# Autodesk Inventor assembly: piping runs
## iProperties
Name: ISO 2531 - Flanged Ductile Iron Pipe and Fittings
ActiveState: False
PipeType: Rigid Pipe
RoutePreview: Solid
Material: UnInitValue
Standard: UnInitValue
FittingMaterial: UnInitValue
FittingStandard: UnInitValue
RouteDirection90: True
RouteDirection45: True
DiameterType: Nominal
Diameter: M40
Schedule: PN10
Ending: UnInitValue
IntermediateSegmentsMin: 1000.000 mm
IntermediateSegmentsMax: 9000.000 mm
IntermediateSegmentsInc: 10.000 mm
TerminationSegmentsMin: 1000.000 mm
TerminationSegmentsMax: 9000.000 mm
TerminationSegmentsInc: 10.000 mm
SolidRoutePreviewColor: 12632064
PipingComponentColor: As Material
PipeKey: v3#f52fbdcb-ece8-4303-8b76-5dbe8c7f2f9c#16
Elbow90Key: v3#451ae64e-c79d-4cba-b533-c09b8090ecb2#1
Elbow45Key: v3#81684a3f-f2a4-4fe6-95b1-f067ddead22f#1
_ComponentInfo: <CS><C N="Pipe" R="2.700000" IR="2.000000" PL="PL" PN="ISO 2531 Pipe with Integrally Cast Flanges DN40 PN 10"><CO N="1"><FE V="0"/><FD V="0"/><ET  V="Flanged"/>
BendRadius: UnInitValue
CategoryName: UnInitValue
DefaultBendRadius: UnInitValue
EndFittingKey: UnInitValue
FlangeKey: UnInitValue
Gap: UnInitValue
GasketKey: UnInitValue
IsButtWelded: UnInitValue
IsFlanged: UnInitValue
MixedUnits: UnInitValue
RoundUpValue: UnInitValue
ShowGap: UnInitValue
StartFittingKey: UnInitValue
SuppressEndFitting: UnInitValue
SuppressStartFitting: UnInitValue
UseFlangsForCouplings: UnInitValue
UseSubASM: UnInitValue
Name: Hydraulic Hose - SAE Flanged Connection
PipeType: Flexible Hose
RouteDirection90: UnInitValue
RouteDirection45: UnInitValue
Diameter: 1/2
Schedule: ID=0.5
OD: 2.235200000000000e+000
ID: 1.270000000000000e+000
IntermediateSegmentsMin: UnInitValue
IntermediateSegmentsMax: UnInitValue
IntermediateSegmentsInc: UnInitValue
TerminationSegmentsMin: UnInitValue
TerminationSegmentsMax: UnInitValue
TerminationSegmentsInc: UnInitValue
RoundUpValue: 0.125 in
PipeKey: v3#d489867e-ac9b-47ea-b952-0a1b885f66be#4
CouplingKey: UnInitValue
Elbow90Key: UnInitValue
Elbow45Key: UnInitValue
_ComponentInfo: <CS><C N="Pipe" R="1.117600" OR="1.117600" IR="0.635000" PL="PL" PartType="" SymKey="" PN="Parker Hydraulic Hose - No Skive 1/2"><CO N="1"><FE V="0"/><FD V="0"/
BendRadius: 0.500 in
StartFittingKey: v3#933069c9-73b6-4141-af99-628d4a97b2c2#1
EndFittingKey: v3#933069c9-73b6-4141-af99-628d4a97b2c2#1
SuppressStartFitting: False
SuppressEndFitting: False
UseSubASM: True
Name: Hydraulic Hose - Female Taper Thread
StartFittingKey: v3#cc3bd835-95a2-497d-9893-176cd9c426f6#7
EndFittingKey: v3#cc3bd835-95a2-497d-9893-176cd9c426f6#7
Name: JIS G 3458/JIS B 2316 -  Welded Steel Pipe and Fittings
Schedule: 80
IntermediateSegmentsMin: 60.000 mm
IntermediateSegmentsMax: 5000.000 mm
IntermediateSegmentsInc: 1.000 mm
TerminationSegmentsMin: 60.000 mm
TerminationSegmentsMax: 5000.000 mm
TerminationSegmentsInc: 1.000 mm
PipeKey: v3#da14b0ab-0b36-4851-8d66-8c9cd0bcbe86#23
CouplingKey: v3#12b64993-10e6-4915-8315-0c0cce209ad0#8
Elbow90Key: v3#1f65ece3-c41a-48d4-8661-909ed34ade86#8
Elbow45Key: v3#28e76e79-e22c-40ab-8be2-ff545b1407c5#8
_ComponentInfo: <CS><C N="Pipe" R="2.430000" IR="1.920000" PL="PL" PN="JIS G 3458 Pipe 40 A x Sch 80"><CO N="1"><FE V="0"/><FD V="1"/><ET V="Welded"/><NS  V="M40"/><MA V="0.000
Name: ASTM A53/A53M-ASME B16.11 - Welded Steel Pipe
Material: Steel
Standard: ASTM A 53/A 53M
FittingMaterial: Steel
FittingStandard: ASME B16.11
Schedule: 40
OD: Undefined
ID: Undefined
IntermediateSegmentsMin: 1.000 in
IntermediateSegmentsMax: 200.000 in
IntermediateSegmentsInc: 0.100 in
TerminationSegmentsMin: 1.000 in
TerminationSegmentsMax: 200.000 in
TerminationSegmentsInc: 0.100 in
PipeKey: v3#4ce5e9fa-6da0-4801-ac02-ee7a0fb518d6#7
CouplingKey: v3#ed415c76-4cec-44a3-ba67-72e47bf70384#4
Elbow90Key: v3#82a08401-12d7-413b-b7f9-9cf3b607be7b#4
Elbow45Key: v3#2e5fd082-3851-4eb0-bde1-6c7078a7d72b#4
_ComponentInfo: <CS><C N="Pipe" R="1.066800" IR="0.789940" PL="PL" PN="ASTM A 53/A 53M Pipe 1/2 - Schedule 40"><CO N="1"><FE V="0"/><FD V="0"/><ET V="Welded"/><NS  V="1/2"/><MA
Diameter: 6
Elbow90Key: v3#97ecdcaf-8aa3-4fb0-8b6a-3da783de2ad5#108
Gap: 0.062 inch
ID: UnInitValue
IntermediateSegmentsInc: 0.00001 in
IntermediateSegmentsMax: 200 inch
IntermediateSegmentsMin: 3 inch
IsButtWelded: True
IsFlanged: False
Name: ASTM A 53/A-ASME B16.9 - Steel Butt Welded Pipe
OD: UnInitValue
PipeKey: v3#4ce5e9fa-6da0-4801-ac02-ee7a0fb518d6#77
RouteDirection45: False
ShowGap: True
TerminationSegmentsInc: 0.00001 in
TerminationSegmentsMax: 200 inch
TerminationSegmentsMin: 3 inch
_ComponentInfo: <CS><C N="Elbow90" ER="15.240000" S1="15.240000" S2="15.240000" D1="0.000000" D2="0.000000" PartType="fitting" SymKey="ELBW"><CO N="1"><FE V="2"/><FD V="0"/><ET
MixedUnits: False
Created: 2006-09
Part Number: piping runs
Document SubType Name: Tube & Pipe
Designer: Autodesk
Manufacturer: Standard
Standards Organization: Custom
Angle: 92.00 deg
Diameter: 1
Elbow45Key: v3#bf26aa2a-f3dd-474c-8758-922a145c2b02#15
Elbow90Key: v3#3e93288f-9bb7-4e46-9d6b-544f8c20ca1c#3
ElbowCustomKey: v3#1f3bd44a-47ab-42f9-b3e0-74afa0c3f0ca#3
Gap: 0.094 in
IntermediateSegmentsMin: 2.000 in
IsSelfDraining: True
Name: ASME BPE - Butt Welded
PipeKey: v3#b10c956f-6fc6-429e-8056-0864a8581764#35
Schedule: ID=0.87
TerminationSegmentsMin: 2.000 in
_ComponentInfo: <CS><C N="Pipe" R="1.270000" OR="1.270000" IR="1.104900" PL="PL" PartType="pipe" SymKey="" PN="ASTM A 269 Tube with Welded ends 1 x 0.87"><CO N="1"><FE V="2"/><
Elbow90Key: v3#6a678020-d9d9-4685-bba9-906b9a167083#10
FlangeKey: v3#c11442d2-c568-438f-a870-8ac9b5b636cb#10
GasketKey: v3#2a41914c-f5fb-4682-9c6a-1870d826d3d0#23
IntermediateSegmentsInc: 0.1 inch
IsButtWelded: False
IsFlanged: True
Name: ASTM A 53/A-ASME B16.5 - Flanged Steel Threaded Pipe
PipeKey: v3#c5bd7d28-cdb3-4507-9f3d-c2787d93fe8a#40
TerminationSegmentsInc: 0.1 inch
_ComponentInfo: <CS><C N="Elbow90" ER="21.590000" S1="21.590000" S2="21.590000" D1="0.000000" D2="0.000000" PartType="fitting" SymKey="ELFL"><CO N="1"><FE V="2"/><FD V="1"/><ET
ElbowCustomKey: UnInitValue
IsSelfDraining: False
Name: ASME B36.10M-ASME B16.11 - Steel Threaded Pipe
ActiveState: True
Material: Wrought Steel
Standard: ASME B36.10M
Schedule: 30
OD: 2.1336
ID: 1.651
PipeKey: v3#4a736116-503a-44ad-a922-868ac6b46736#1
CouplingKey: v3#52ad3977-2b89-4007-a6a6-7626bac0ae85#4
Elbow90Key: v3#160eac10-3e6f-4b5c-839c-61eee0d373dc#4
Elbow45Key: v3#5c2ab816-abcb-49a6-a106-4733af000f51#4
_ComponentInfo: <CS><C N="Pipe" R="1.066800" IR="0.825500" PL="PL" PN="ASME B36.10M Pipe with Threaded Ends 1/2 - Schedule 30"><CO N="1"><FE V="0"/><FD V="1"/><ET  V="Threaded"
Name: DIN 2458/DIN 2605 - Welded Steel Pipe and Fittings
Schedule: ID=30.7
PipeKey: v3#dcef2839-8903-4c98-a96c-b861f5d9bb7f#98
Elbow90Key: v3#ace818b0-7b7c-4ad9-b19c-6da358a202c1#17
Elbow45Key: v3#97879d80-057e-491b-840b-74a9b3a7cf63#17
_ComponentInfo: <CS><C N="Pipe" R="2.415000" IR="1.535000" PL="PL" PN="DIN 2458 Pipe 48.3 x 8.8"><CO N="1"><FE V="2"/><FD V="0"/><ET V="Welded"/><NS V="M40"/><MA  V="0.000000"/
Name: Hydraulic Hose - Male Taper Thread
StartFittingKey: v3#c8250148-a7b6-458b-b7bd-3b56763ca7cc#13
EndFittingKey: v3#c8250148-a7b6-458b-b7bd-3b56763ca7cc#13
Name: JIS G 3442/JIS B 2301 Threaded Steel Pipe and Iron Fittings
Schedule: ID=16.1
IntermediateSegmentsMin: 20.000 mm
TerminationSegmentsMin: 20.000 mm
PipeKey: v3#9964fba4-9d5a-4d75-85a8-e38022ccdce1#2
CouplingKey: v3#181262db-c004-4877-bc40-c64b931a44f6#3
Elbow90Key: v3#6c92b367-65e9-486b-b952-db434ae2548d#3
Elbow45Key: v3#960407aa-00b9-4d72-aae7-d50595845cfd#3
_ComponentInfo: <CS><C N="Pipe" R="1.085000" IR="0.805000" PL="PL" PN="JIS G 3442 Pipe with Threaded Ends 21.7 x 2.8"><CO N="1"><FE V="0"/><FD V="1"/><ET V="Threaded"/><NS V="1
Name: ASTM B 88-ASME B16.22 - Soldered Copper Tubing
PipeType: Tubing
Material: Copper
Standard: ASTM B 88
FittingMaterial: *
FittingStandard: ASME B16.22
Schedule: L
IntermediateSegmentsMin: 0.000 in
IntermediateSegmentsMax: 100.000 in
TerminationSegmentsMin: 0.000 in
TerminationSegmentsMax: 100.000 in
SolidRoutePreviewColor: 49344
PipeKey: v3#44b182c9-4bce-4825-bb4d-596143122252#7
CouplingKey: v3#0dc1ae02-7bbf-4ccf-8498-581434b0a765#3
_ComponentInfo: <CS><C N="Pipe" R="0.793750" IR="0.692150" PL="PL" PN="ASTM B 88 Tube 1/2 - Type L"><CO N="1"><FE V="0"/><FD V="0"/><ET V="Soldered"/><NS V="1/2"/><MA V="2.5400
DefaultBendRadius: 2.000 in
Name: ISO 7598/ISO 49 - Threaded Steel Pipe with Iron Fittings
IntermediateSegmentsMin: 50.800 mm
IntermediateSegmentsMax: 5080.000 mm
IntermediateSegmentsInc: 2.540 mm
TerminationSegmentsMin: 50.800 mm
TerminationSegmentsMax: 5080.000 mm
TerminationSegmentsInc: 2.540 mm
PipeKey: v3#1052637f-74b5-47f4-adeb-d4e8d3fa53b8#1
CouplingKey: v3#7e56b2cb-a132-4546-b8a7-a14538454b94#3
Elbow90Key: v3#b72bb08b-ad33-47cc-a03d-7f3d76c6616b#3
Elbow45Key: v3#a96c5204-26e4-4bb2-b8f1-f0623fbc94bb#2
_ComponentInfo: <CS><C N="Pipe" R="1.065000" IR="0.805000" PL="PL" PN="ISO 7598 Tube with Threaded Ends DN15"><CO N="1"><FE V="0"/><FD V="1"/><ET V="Threaded"/><NS V="1/2"/><MA
FlangeKey: v3#24991861-26e3-4c21-a713-f46e314eddd5#10
IntermediateSegmentsMin: 3.000 in
Name: ASTM A 53/A 53M - Butt Welded/Flanged Steel Pipe
TerminationSegmentsMin: 3.000 in
UseFlangsForCouplings: False
_ComponentInfo: <CS><C N="Pipe" R="8.413750" OR="8.413750" IR="7.702550" PL="PL" PartType="pipe" SymKey="" PN="ASTM A 53/A 53M Pipe 6 - Schedule 40"><CO N="1"><FE V="2"/><FD V=
Name: JIS K 6741/JIS K 6739 - Jointed PVC-U Pipe and Fittings
Schedule: VP
IntermediateSegmentsMax: 2500.000 mm
TerminationSegmentsMax: 2500.000 mm
PipeKey: v3#45338dd0-af69-48c0-a2ed-8ade33a08701#5
CouplingKey: v3#eaa8de87-dc67-4eca-ba7e-4267a30f8f7f#2
Elbow90Key: v3#c4513a61-3106-4a78-baf9-a1badd100245#2
Elbow45Key: v3#2769403e-a4fd-4a4c-8e4c-659ea845bd78#2
_ComponentInfo: <CS><C N="Pipe" R="2.400000" IR="2.040000" PL="PL" PN="JIS K 6741 Pipe VP 40"><CO N="1"><FE V="0"/><FD V="1"/><ET V="Jointed"/><NS V="M40"/><MA  V="4.000000"/><
Name: Hydraulic Hose - Female Thread - Swivel
StartFittingKey: v3#c5e461f5-5e73-4f2e-8c1e-4358d4d6f46c#4
EndFittingKey: v3#c5e461f5-5e73-4f2e-8c1e-4358d4d6f46c#4
Name: ASTM D 1785-ASTM D 2466 - Jointed PVC Pipe and Fittings
Material: PVC-Piping
Standard: ASTM D 1785
FittingMaterial: PVC-Piping
FittingStandard: ASTM D 2466
PipeKey: v3#4bf12049-4375-491b-8f13-d4ee0c517c57#1
CouplingKey: v3#29993622-4c6a-437e-8b8c-43a0846f8735#1
Elbow90Key: v3#25d2a8db-6517-4627-a5a4-9d27e4d26b9b#1
Elbow45Key: v3#d7b5d569-4a12-4d65-ba55-12203d6ac7ed#1
_ComponentInfo: <CS><C N="Pipe" R="1.066800" IR="0.789940" PL="PL" PN="ASTM D 1785 Pipe 1/2 - Schedule 40"><CO N="1"><FE V="0"/><FD V="0"/><ET V="Jointed"/><NS  V="1/2"/><MA V=
Name: DIN 2458/DIN EN 10242 - Threaded Steel Pipe and Iron Fittings
Schedule: ID=12.3
PipeKey: v3#d689fd5f-ac5a-46d7-a883-3089b2f6e0a4#28
CouplingKey: v3#d2599e7a-1865-48da-a234-5418a1cd5dfe#3
Elbow90Key: v3#9fba244e-81ed-4fc6-a9ac-7eb372fa3ffe#3
Elbow45Key: v3#6ce5b1be-37aa-4928-b23a-0df64e6ddf38#2
_ComponentInfo: <CS><C N="Pipe" R="1.065000" IR="0.615000" PL="PL" PN="DIN 2458 Pipe with Threaded Ends 21.3 x 4.5"><CO N="1"><FE V="0"/><FD V="1"/><ET V="Threaded"/><NS V="1/2
count: 29
Refkey_Axis1_Context: 2|0|0|0|1|0|0|0|
Refkey_Axis1: 6|0|0|0|44|0|0|0|78|0|65|0|77|0|69|0|83|0|10|0|67|0|111|0|108|0|111|0|114|0|115|0|10|0|49|0|58|0|10|0|10|0|69|0|78|0|68|0|10|0|0|0|
Refkey_Axis2_Context: 2|0|0|0|1|0|0|0|
Refkey_Axis2: 6|0|0|0|88|0|0|0|78|0|65|0|77|0|69|0|83|0|10|0|67|0|111|0|108|0|111|0|114|0|115|0|10|0|49|0|58|0|82|0|111|0|117|0|116|0|101|0|32|0|85|0|73|0|32|0|84|0|111|0|111
Refkey_Axis3_Context: 2|0|0|0|1|0|0|0|
Refkey_Axis3: 6|0|0|0|88|0|0|0|78|0|65|0|77|0|69|0|83|0|10|0|67|0|111|0|108|0|111|0|114|0|115|0|10|0|49|0|58|0|82|0|111|0|117|0|116|0|101|0|32|0|85|0|73|0|32|0|84|0|111|0|111
Refkey_Ext_Context: 2|0|0|0|1|0|0|0|
Refkey_Ext: 6|0|0|0|92|0|0|0|78|0|65|0|77|0|69|0|83|0|10|0|67|0|111|0|108|0|111|0|114|0|115|0|10|0|49|0|58|0|82|0|111|0|117|0|116|0|101|0|32|0|85|0|73|0|32|0|84|0|111|0|111
Refkey_Snap_Context: 2|0|0|0|1|0|0|0|
Refkey_Snap: 6|0|0|0|84|0|0|0|78|0|65|0|77|0|69|0|83|0|10|0|67|0|111|0|108|0|111|0|114|0|115|0|10|0|49|0|58|0|82|0|111|0|117|0|116|0|101|0|32|0|85|0|73|0|32|0|84|0|111|0|111
Name: DIN 8062/DIN 8063 - Jointed PVC-U Pipe and Fittings
Schedule: 5
PipeKey: v3#3d294dc7-89c3-4c37-a0ae-28c15a73bfd0#13
CouplingKey: v3#3edf83e2-464b-4b31-84c5-c329ffbf2a4f#5
Elbow90Key: v3#fbd68fd5-590c-4cb5-8c20-9e9bdd396a04#5
Elbow45Key: v3#2f597a97-b15b-49d4-87cb-7bfe69eb62ee#5
_ComponentInfo: <CS><C N="Pipe" R="2.000000" IR="1.700000" PL="PL" PN="DIN 8062 Pipe 40 x 3"><CO N="1"><FE V="0"/><FD V="0"/><ET V="Jointed"/><NS V="M40"/><MA  V="8.000000"/><M
Name: ANSI/ASME B36.19M-ASME B16.3 - Threaded Pipe with Iron Fittings
Material: Stainless Steel
Standard: ANSI/ASME B36.19M
FittingMaterial: Malleable Iron
FittingStandard: ASME B16.3
Schedule: 40S
PipeKey: v3#323c0148-c750-449d-a0c6-11721f2a5046#1
CouplingKey: v3#771d4942-b9e7-43bc-9d41-ab12a9580492#3
Elbow90Key: v3#bc6b44ab-9235-4590-b699-74498030a1ff#3
Elbow45Key: v3#626cc28c-1a24-4045-be0d-40d896dc828d#3
_ComponentInfo: <CS><C N="Pipe" R="1.066800" IR="0.789940" PL="PL" PN="ANSI/ASME B36.19M Pipe with Threaded Ends 1/2 - Schedule 40S"><CO N="1"><FE V="0"/><FD  V="1"/><ET V="Thr
Name: Hydraulic Hose - Male Straight Thread
StartFittingKey: v3#b50cb43e-68c0-48ac-8e25-7ef224ce0e6c#3
EndFittingKey: v3#b50cb43e-68c0-48ac-8e25-7ef224ce0e6c#3
Name: ISO 4065-ISO 3633 - PVC Pipe and Fittings
Schedule: S40
IntermediateSegmentsMax: 2540.000 mm
TerminationSegmentsMax: 2540.000 mm
PipeKey: v3#4f84f716-5ba0-45ef-967a-c32c3d7345ce#70
CouplingKey: v3#b06656e5-2b55-488c-bcf0-6a90c79c4683#2
Elbow90Key: v3#17490b17-1dd8-40fc-8de7-1a70c3bab2d7#1
Elbow45Key: v3#421a8b99-1721-409a-bc3b-c00889561754#1
_ComponentInfo: <CS><C N="Pipe" R="2.000000" IR="1.950000" PL="PL" PN="ISO 4065 Pipe 40 x 0.5 S40"><CO N="1"><FE V="0"/><FD V="0"/><ET V="Jointed"/><NS V="M40"/><MA  V="6.00000
Name: Hydraulic Hose - No Fittings
SuppressStartFitting: True
SuppressEndFitting: True
Author: Autodesk
